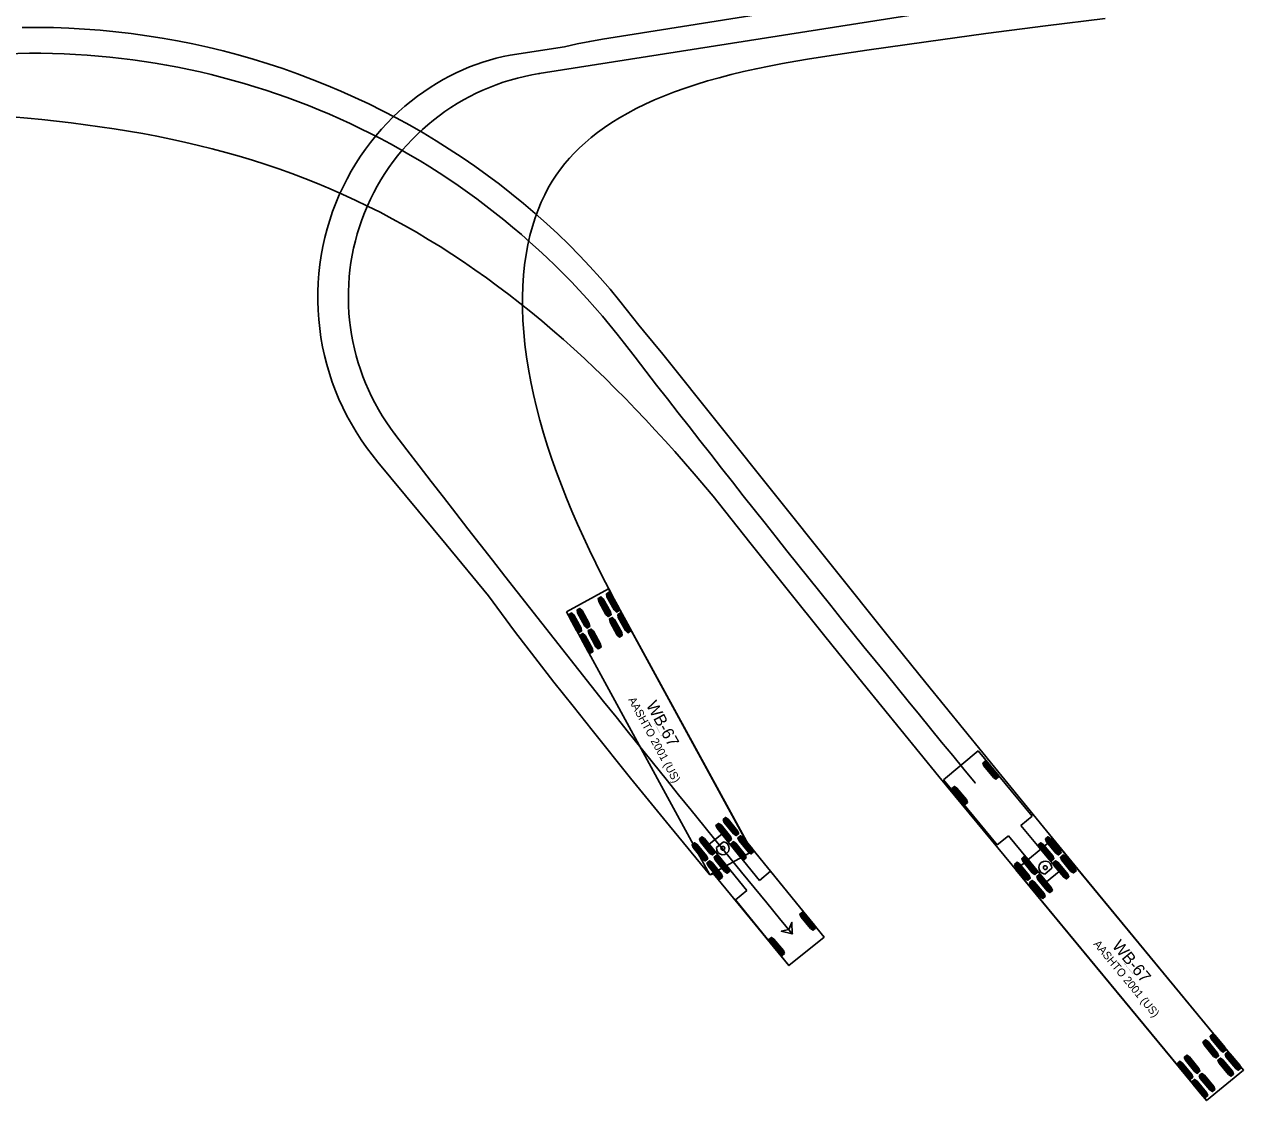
# Model space of a CAD drawing. Extents: x 1639988 to 1641860, y 841974 to 844187.
# Drawn here: x 1640960 to 1641175.9, y 842500.3 to 842690.9 of the extents above; entities that cross this region are included whole.
import ezdxf

# ---------------------------------------------------------------- set-up
doc = ezdxf.new("R2010")
doc.units = 0
doc.layers.add('Scratch_Level_1', color=7, linetype='Continuous')

msp = doc.modelspace()

# ---------------------------------------------------------------- linework, layer by layer
at = {"layer": 'Scratch_Level_1'}
for p, q in [((1641139.5, 842696.08), (1641051.19, 842682.18)), ((1641063.48, 842590.91), (1641056.02, 842586.84)), ((1641088.89, 842544.4), (1641063.48, 842590.91)), ((1641063.47, 842586.06), (1641061.71, 842589.28)), ((1641063.67, 842586.17), (1641061.91, 842589.39)), ((1641063.87, 842586.28), (1641062.11, 842589.5)), ((1641064.92, 842586.85), (1641063.16, 842590.07)), ((1641065.12, 842586.96), (1641063.36, 842590.18)), ((1641065.32, 842587.07), (1641063.56, 842590.29)), ((1641056.02, 842586.84), (1641081.43, 842540.32)), ((1641058.66, 842583.44), (1641056.91, 842586.65)), ((1641059.71, 842584.01), (1641057.95, 842587.23)), ((1641059.91, 842584.12), (1641058.15, 842587.34)), ((1641060.11, 842584.23), (1641058.36, 842587.45)), ((1641067.32, 842583.41), (1641065.56, 842586.63)), ((1641058.26, 842583.22), (1641056.5, 842586.44)), ((1641058.46, 842583.33), (1641056.71, 842586.55)), ((1641065.47, 842582.4), (1641063.71, 842585.62)), ((1641065.67, 842582.51), (1641063.91, 842585.73)), ((1641065.87, 842582.62), (1641064.11, 842585.84)), ((1641066.92, 842583.2), (1641065.16, 842586.41)), ((1641067.12, 842583.3), (1641065.36, 842586.52)), ((1641060.26, 842579.56), (1641058.5, 842582.78)), ((1641060.46, 842579.67), (1641058.7, 842582.89)), ((1641060.66, 842579.78), (1641058.9, 842583)), ((1641061.71, 842580.35), (1641059.95, 842583.57)), ((1641061.91, 842580.46), (1641060.15, 842583.68)), ((1641062.11, 842580.57), (1641060.35, 842583.79)), ((1641128.94, 842562.23), (1641122.77, 842557.14)), ((1641138.49, 842550.67), (1641128.94, 842562.23)), ((1641129.79, 842560.13), (1641132.12, 842557.3)), ((1641129.96, 842560.27), (1641132.3, 842557.45)), ((1641130.14, 842560.42), (1641132.47, 842557.59)), ((1641122.77, 842557.14), (1641132.32, 842545.58)), ((1641122.77, 842557.14), (1641122.77, 842557.14)), ((1641124.32, 842555.62), (1641126.66, 842552.79)), ((1641124.5, 842555.76), (1641126.84, 842552.93)), ((1641124.68, 842555.91), (1641127.01, 842553.08)), ((1641086.13, 842547.28), (1641083.82, 842550.12)), ((1641086.31, 842547.42), (1641084, 842550.27)), ((1641086.49, 842547.56), (1641084.18, 842550.41)), ((1641136.51, 842549.04), (1641138.49, 842550.67)), ((1641084.85, 842546.23), (1641082.54, 842549.08)), ((1641085.03, 842546.38), (1641082.72, 842549.22)), ((1641085.21, 842546.52), (1641082.9, 842549.37)), ((1641143.25, 842540.88), (1641136.51, 842549.04)), ((1641080.64, 842542.81), (1641078.32, 842545.65)), ((1641080.81, 842542.95), (1641078.5, 842545.8)), ((1641080.99, 842543.1), (1641078.68, 842545.94)), ((1641081.92, 842543.85), (1641079.6, 842546.69)), ((1641082.09, 842543.99), (1641079.78, 842546.84)), ((1641082.27, 842544.14), (1641079.96, 842546.98)), ((1641083.52, 842547.51), (1641081.29, 842545.71)), ((1641081.29, 842545.71), (1641087.97, 842537.49)), ((1641083.84, 842546.13), (1641082.58, 842545.11)), ((1641090.19, 842539.3), (1641083.52, 842547.51)), ((1641087.48, 842543), (1641085.17, 842545.85)), ((1641087.66, 842543.15), (1641085.35, 842545.99)), ((1641087.84, 842543.29), (1641085.52, 842546.14)), ((1641088.76, 842544.04), (1641086.45, 842546.89)), ((1641088.94, 842544.19), (1641086.63, 842547.03)), ((1641089.12, 842544.33), (1641086.8, 842547.18)), ((1641132.32, 842545.58), (1641134.3, 842547.21)), ((1641134.3, 842547.21), (1641141.04, 842539.05)), ((1641142.18, 842546.59), (1641135.63, 842541.18)), ((1641139.6, 842545.65), (1641141.94, 842542.82)), ((1641139.78, 842545.79), (1641142.12, 842542.97)), ((1641139.96, 842545.94), (1641142.29, 842543.11)), ((1641140.88, 842546.7), (1641143.21, 842543.87)), ((1641141.05, 842546.84), (1641143.39, 842544.02)), ((1641141.23, 842546.99), (1641143.56, 842544.16)), ((1641175.93, 842505.72), (1641142.18, 842546.59)), ((1641081.43, 842540.32), (1641088.89, 842544.4)), ((1641084.54, 842540.62), (1641082.23, 842543.46)), ((1641084.72, 842540.76), (1641082.41, 842543.61)), ((1641084.9, 842540.9), (1641082.59, 842543.75)), ((1641088.89, 842544.4), (1641088.89, 842544.4)), ((1641136.86, 842543.38), (1641139.2, 842540.56)), ((1641137.04, 842543.53), (1641139.38, 842540.7)), ((1641143.53, 842543.49), (1641145.86, 842540.66)), ((1641143.71, 842543.63), (1641146.04, 842540.8)), ((1641143.88, 842543.78), (1641146.22, 842540.95)), ((1641083.26, 842539.57), (1641080.95, 842542.42)), ((1641083.44, 842539.72), (1641081.13, 842542.57)), ((1641083.62, 842539.86), (1641081.31, 842542.71)), ((1641135.42, 842542.19), (1641137.75, 842539.36)), ((1641135.59, 842542.33), (1641137.93, 842539.51)), ((1641135.77, 842542.48), (1641138.1, 842539.65)), ((1641136.69, 842543.24), (1641139.02, 842540.41)), ((1641140.71, 842540.43), (1641141.95, 842541.46)), ((1641142.26, 842542.43), (1641144.59, 842539.61)), ((1641142.43, 842542.58), (1641144.77, 842539.75)), ((1641142.61, 842542.73), (1641144.95, 842539.9)), ((1641092.18, 842540.92), (1641090.19, 842539.3)), ((1641101.64, 842529.28), (1641092.18, 842540.92)), ((1641135.63, 842541.18), (1641169.38, 842500.31)), ((1641135.63, 842541.18), (1641135.63, 842541.18)), ((1641138.25, 842539.12), (1641140.58, 842536.29)), ((1641138.42, 842539.27), (1641140.76, 842536.44)), ((1641139.34, 842540.03), (1641141.68, 842537.2)), ((1641139.52, 842540.17), (1641141.85, 842537.34)), ((1641139.69, 842540.32), (1641142.03, 842537.49)), ((1641141.04, 842539.05), (1641143.25, 842540.88)), ((1641087.97, 842537.49), (1641085.98, 842535.87)), ((1641138.07, 842538.97), (1641140.4, 842536.15)), ((1641085.98, 842535.87), (1641095.43, 842524.23)), ((1641099.75, 842530.53), (1641097.42, 842533.36)), ((1641099.93, 842530.68), (1641097.59, 842533.51)), ((1641100.11, 842530.83), (1641097.77, 842533.65)), ((1641094.26, 842526.06), (1641091.93, 842528.89)), ((1641094.44, 842526.21), (1641092.1, 842529.04)), ((1641094.61, 842526.35), (1641092.28, 842529.18)), ((1641095.43, 842524.23), (1641101.64, 842529.28)), ((1641101.64, 842529.28), (1641101.64, 842529.28)), ((1641169.13, 842511.02), (1641171.46, 842508.19)), ((1641170.04, 842511.78), (1641172.38, 842508.95)), ((1641170.22, 842511.92), (1641172.56, 842509.09)), ((1641170.4, 842512.07), (1641172.73, 842509.24)), ((1641168.77, 842510.72), (1641171.11, 842507.9)), ((1641168.95, 842510.87), (1641171.28, 842508.04)), ((1641173.05, 842508.85), (1641175.39, 842506.03)), ((1641164.2, 842506.95), (1641166.53, 842504.12)), ((1641164.37, 842507.09), (1641166.71, 842504.27)), ((1641164.55, 842507.24), (1641166.89, 842504.41)), ((1641165.47, 842508), (1641167.8, 842505.17)), ((1641165.65, 842508.14), (1641167.98, 842505.32)), ((1641165.82, 842508.29), (1641168.16, 842505.46)), ((1641171.43, 842507.51), (1641173.76, 842504.69)), ((1641171.6, 842507.66), (1641173.94, 842504.83)), ((1641171.78, 842507.8), (1641174.11, 842504.98)), ((1641172.7, 842508.56), (1641175.03, 842505.74)), ((1641172.87, 842508.71), (1641175.21, 842505.88)), ((1641168.12, 842504.78), (1641170.46, 842501.96)), ((1641168.3, 842504.93), (1641170.63, 842502.1)), ((1641168.48, 842505.08), (1641170.81, 842502.25)), ((1641169.38, 842500.31), (1641175.93, 842505.72)), ((1641166.85, 842503.73), (1641169.19, 842500.91)), ((1641167.03, 842503.88), (1641169.36, 842501.05)), ((1641167.2, 842504.03), (1641169.54, 842501.2))]:
    msp.add_line(p, q, dxfattribs=at)
for points in [[(1641151.4, 842691.94), (1641140.84, 842690.63), (1641130.29, 842689.25), (1641119.74, 842687.81), (1641109.22, 842686.33), (1641104.09, 842685.57), (1641099.09, 842684.78), (1641096.65, 842684.37), (1641094.26, 842683.94), (1641091.91, 842683.49), (1641089.62, 842683.02), (1641087.38, 842682.52), (1641085.19, 842682), (1641083.07, 842681.45), (1641081, 842680.87), (1641079, 842680.26), (1641077.06, 842679.62), (1641075.19, 842678.95), (1641073.38, 842678.25), (1641071.65, 842677.52), (1641069.98, 842676.76), (1641068.39, 842675.98), (1641066.87, 842675.17), (1641065.43, 842674.34), (1641064.06, 842673.49), (1641062.76, 842672.62), (1641061.54, 842671.74), (1641060.4, 842670.84), (1641059.32, 842669.93), (1641058.33, 842669.02), (1641057.41, 842668.11), (1641056.55, 842667.19), (1641055.73, 842666.24), (1641054.95, 842665.24), (1641054.21, 842664.2), (1641053.5, 842663.1), (1641052.82, 842661.95), (1641052.18, 842660.73), (1641051.57, 842659.43), (1641051, 842658.07), (1641050.48, 842656.63), (1641050, 842655.12), (1641049.57, 842653.53), (1641049.2, 842651.87), (1641048.88, 842650.14), (1641048.62, 842648.34), (1641048.43, 842646.48), (1641048.3, 842644.56), (1641048.24, 842642.58), (1641048.24, 842640.55), (1641048.32, 842638.48), (1641048.46, 842636.37), (1641048.67, 842634.22), (1641048.96, 842632.03), (1641049.3, 842629.83), (1641049.72, 842627.59), (1641050.19, 842625.34), (1641050.73, 842623.08), (1641051.33, 842620.8), (1641051.98, 842618.51), (1641052.7, 842616.21), (1641053.46, 842613.91), (1641054.27, 842611.6), (1641055.14, 842609.29), (1641056.05, 842606.99), (1641057, 842604.68), (1641057.99, 842602.38), (1641059.03, 842600.08), (1641060.1, 842597.78), (1641061.21, 842595.49), (1641062.35, 842593.21), (1641063.52, 842590.93), (1641064.73, 842588.65), (1641087.87, 842546.25), (1641088.05, 842545.99), (1641101.64, 842529.28), (1641095.43, 842524.23), (1641088.6, 842532.5), (1641082.06, 842540.48), (1641081.43, 842540.32), (1641074.29, 842548.99), (1641067.4, 842557.42), (1641060.57, 842565.89), (1641057.19, 842570.14), (1641053.82, 842574.4), (1641050.44, 842578.75), (1641046.86, 842583.43), (1641042.2, 842589.68), (1641034.74, 842598.79), (1641022.66, 842613.35), (1641021.62, 842614.65), (1641020.62, 842615.98), (1641019.67, 842617.33), (1641018.78, 842618.72), (1641017.94, 842620.13), (1641017.16, 842621.56), (1641016.43, 842623.03), (1641015.75, 842624.51), (1641015.13, 842626.02), (1641014.56, 842627.55), (1641014.05, 842629.09), (1641013.59, 842630.65), (1641013.19, 842632.23), (1641012.85, 842633.82), (1641012.56, 842635.42), (1641012.34, 842637.03), (1641012.17, 842638.65), (1641012.06, 842640.27), (1641012, 842641.89), (1641012.01, 842643.51), (1641012.07, 842645.14), (1641012.19, 842646.75), (1641012.37, 842648.36), (1641012.61, 842649.96), (1641012.9, 842651.55), (1641013.25, 842653.13), (1641013.66, 842654.68), (1641014.12, 842656.22), (1641014.63, 842657.74), (1641015.19, 842659.23), (1641015.81, 842660.69), (1641016.47, 842662.12), (1641017.18, 842663.53), (1641017.93, 842664.9), (1641018.73, 842666.23), (1641019.56, 842667.53), (1641020.44, 842668.78), (1641021.35, 842670), (1641022.29, 842671.18), (1641023.27, 842672.31), (1641024.27, 842673.4), (1641025.3, 842674.44), (1641026.35, 842675.44), (1641027.43, 842676.39), (1641028.52, 842677.29), (1641029.63, 842678.15), (1641030.76, 842678.96), (1641031.89, 842679.73), (1641033.03, 842680.45), (1641034.19, 842681.12), (1641035.35, 842681.74), (1641036.51, 842682.32), (1641037.68, 842682.86), (1641038.85, 842683.35), (1641040.02, 842683.8), (1641041.2, 842684.2), (1641042.4, 842684.57), (1641043.61, 842684.9), (1641044.84, 842685.18), (1641046.08, 842685.42), (1641055.69, 842686.94), (1641057.92, 842687.42), (1641060.16, 842687.86), (1641062.4, 842688.26), (1641066.92, 842689), (1641105.61, 842695.11)], [(1640959.66, 842690.34), (1640962.42, 842690.36), (1640965.18, 842690.31), (1640967.94, 842690.22), (1640970.7, 842690.06), (1640973.46, 842689.86), (1640976.22, 842689.59), (1640978.97, 842689.27), (1640981.7, 842688.89), (1640984.43, 842688.46), (1640987.15, 842687.98), (1640989.86, 842687.43), (1640992.56, 842686.84), (1640995.25, 842686.19), (1640997.92, 842685.48), (1641000.58, 842684.72), (1641003.22, 842683.91), (1641005.83, 842683.05), (1641008.43, 842682.13), (1641011, 842681.16), (1641013.55, 842680.15), (1641016.07, 842679.08), (1641018.57, 842677.97), (1641021.03, 842676.81), (1641023.48, 842675.59), (1641025.9, 842674.33), (1641028.29, 842673.02), (1641030.65, 842671.67), (1641032.99, 842670.27), (1641035.29, 842668.82), (1641037.56, 842667.32), (1641039.8, 842665.78), (1641042.01, 842664.2), (1641044.18, 842662.57), (1641046.32, 842660.9), (1641048.42, 842659.19), (1641050.48, 842657.43), (1641052.51, 842655.63), (1641054.49, 842653.79), (1641056.43, 842651.91), (1641058.34, 842649.99), (1641060.19, 842648.03), (1641062.01, 842646.02), (1641063.77, 842643.98), (1641065.49, 842641.9), (1641068.83, 842637.65), (1641069.66, 842636.6), (1641071.38, 842634.55), (1641073.07, 842632.48), (1641112.99, 842582.57), (1641119.67, 842574.29), (1641126.37, 842566.02), (1641133.1, 842557.76), (1641146.59, 842541.29), (1641160.14, 842524.85), (1641175.93, 842505.72), (1641169.38, 842500.31), (1641169.28, 842500.43), (1641169.28, 842500.43)], [(1641169.28, 842500.43), (1641128.76, 842549.5), (1641121.99, 842557.73), (1641115.23, 842565.98), (1641108.5, 842574.26), (1641101.79, 842582.55), (1641095.12, 842590.86), (1641088.52, 842599.14), (1641082, 842607.37), (1641078.63, 842611.33), (1641075.21, 842615.23), (1641073.49, 842617.15), (1641071.75, 842619.05), (1641070, 842620.93), (1641068.24, 842622.78), (1641066.46, 842624.62), (1641064.67, 842626.43), (1641062.87, 842628.22), (1641061.04, 842629.98), (1641059.21, 842631.71), (1641057.35, 842633.42), (1641055.48, 842635.1), (1641053.58, 842636.75), (1641051.68, 842638.37), (1641049.75, 842639.96), (1641047.8, 842641.52), (1641045.84, 842643.05), (1641043.85, 842644.55), (1641041.85, 842646.01), (1641039.83, 842647.44), (1641037.79, 842648.84), (1641035.74, 842650.2), (1641033.66, 842651.53), (1641031.57, 842652.82), (1641029.46, 842654.07), (1641027.33, 842655.29), (1641025.18, 842656.47), (1641023.02, 842657.61), (1641020.83, 842658.71), (1641018.64, 842659.77), (1641016.43, 842660.79), (1641014.2, 842661.78), (1641011.96, 842662.72), (1641009.7, 842663.62), (1641007.42, 842664.48), (1641005.12, 842665.31), (1641002.79, 842666.09), (1641000.45, 842666.84), (1640998.08, 842667.55), (1640995.7, 842668.22), (1640993.29, 842668.86), (1640990.87, 842669.46), (1640988.42, 842670.03), (1640985.96, 842670.57), (1640983.49, 842671.07), (1640981, 842671.54), (1640978.49, 842671.97), (1640975.97, 842672.38), (1640973.43, 842672.76), (1640970.88, 842673.12), (1640968.31, 842673.44), (1640965.74, 842673.75), (1640963.16, 842674.02), (1640960.57, 842674.28), (1640957.97, 842674.51)], [(1641096.02, 842529.86), (1641095.94, 842531.86), (1641095.38, 842530.63), (1641094.07, 842530.31), (1641096.02, 842529.86)]]:
    msp.add_lwpolyline(points, dxfattribs=at)
for points in [[(1641063.92, 842586.31), (1641063.42, 842586.03), (1641063.02, 842586.4), (1641061.76, 842588.72), (1641061.66, 842589.25), (1641062.16, 842589.53), (1641062.56, 842589.16), (1641063.83, 842586.84)], [(1641065.37, 842587.1), (1641064.87, 842586.82), (1641064.47, 842587.19), (1641063.21, 842589.51), (1641063.11, 842590.04), (1641063.61, 842590.32), (1641064.01, 842589.95), (1641065.28, 842587.63)], [(1641058.71, 842583.46), (1641058.21, 842583.19), (1641057.82, 842583.56), (1641056.55, 842585.87), (1641056.46, 842586.41), (1641056.96, 842586.68), (1641057.35, 842586.31), (1641058.62, 842584)], [(1641060.16, 842584.25), (1641059.66, 842583.98), (1641059.26, 842584.35), (1641058, 842586.67), (1641057.9, 842587.2), (1641058.41, 842587.47), (1641058.8, 842587.11), (1641060.07, 842584.79)], [(1641067.37, 842583.44), (1641066.87, 842583.17), (1641066.47, 842583.54), (1641065.2, 842585.85), (1641065.11, 842586.39), (1641065.61, 842586.66), (1641066.01, 842586.29), (1641067.27, 842583.98)], [(1641065.92, 842582.65), (1641065.42, 842582.38), (1641065.02, 842582.74), (1641063.75, 842585.06), (1641063.66, 842585.6), (1641064.16, 842585.87), (1641064.56, 842585.5), (1641065.82, 842583.18)], [(1641060.71, 842579.81), (1641060.21, 842579.53), (1641059.81, 842579.9), (1641058.55, 842582.22), (1641058.45, 842582.75), (1641058.95, 842583.03), (1641059.35, 842582.66), (1641060.62, 842580.34)], [(1641062.16, 842580.6), (1641061.66, 842580.32), (1641061.26, 842580.69), (1641060, 842583.01), (1641059.9, 842583.54), (1641060.4, 842583.82), (1641060.8, 842583.45), (1641062.07, 842581.13)], [(1641129.74, 842560.09), (1641130.18, 842560.45), (1641130.64, 842560.17), (1641132.32, 842558.13), (1641132.52, 842557.63), (1641132.08, 842557.26), (1641131.62, 842557.55), (1641129.94, 842559.58)], [(1641124.28, 842555.58), (1641124.72, 842555.94), (1641125.18, 842555.66), (1641126.86, 842553.62), (1641127.06, 842553.12), (1641126.62, 842552.75), (1641126.16, 842553.04), (1641124.47, 842555.07)], [(1641086.53, 842547.6), (1641086.09, 842547.24), (1641085.63, 842547.53), (1641083.97, 842549.58), (1641083.78, 842550.09), (1641084.22, 842550.45), (1641084.68, 842550.16), (1641086.34, 842548.11)], [(1641085.25, 842546.56), (1641084.81, 842546.2), (1641084.35, 842546.49), (1641082.69, 842548.54), (1641082.5, 842549.04), (1641082.94, 842549.41), (1641083.4, 842549.12), (1641085.06, 842547.07)], [(1641081.04, 842543.13), (1641080.59, 842542.77), (1641080.13, 842543.06), (1641078.47, 842545.11), (1641078.28, 842545.62), (1641078.72, 842545.98), (1641079.18, 842545.69), (1641080.85, 842543.64)], [(1641082.32, 842544.17), (1641081.87, 842543.81), (1641081.41, 842544.1), (1641079.75, 842546.15), (1641079.56, 842546.66), (1641080, 842547.02), (1641080.46, 842546.73), (1641082.13, 842544.68)], [(1641087.88, 842543.33), (1641087.44, 842542.96), (1641086.98, 842543.25), (1641085.31, 842545.3), (1641085.12, 842545.81), (1641085.57, 842546.17), (1641086.03, 842545.88), (1641087.69, 842543.83)], [(1641089.16, 842544.37), (1641088.72, 842544.01), (1641088.26, 842544.3), (1641086.59, 842546.34), (1641086.4, 842546.85), (1641086.85, 842547.21), (1641087.31, 842546.92), (1641088.97, 842544.87)], [(1641139.56, 842545.61), (1641140, 842545.98), (1641140.46, 842545.69), (1641142.14, 842543.65), (1641142.34, 842543.15), (1641141.9, 842542.78), (1641141.44, 842543.07), (1641139.75, 842545.11)], [(1641140.83, 842546.66), (1641141.27, 842547.03), (1641141.73, 842546.74), (1641143.41, 842544.7), (1641143.61, 842544.2), (1641143.17, 842543.83), (1641142.71, 842544.12), (1641141.03, 842546.16)], [(1641084.94, 842540.94), (1641084.5, 842540.58), (1641084.04, 842540.87), (1641082.38, 842542.92), (1641082.19, 842543.43), (1641082.63, 842543.79), (1641083.09, 842543.5), (1641084.75, 842541.45)], [(1641136.64, 842543.2), (1641137.08, 842543.57), (1641137.54, 842543.28), (1641139.23, 842541.24), (1641139.42, 842540.74), (1641138.98, 842540.37), (1641138.52, 842540.66), (1641136.84, 842542.7)], [(1641143.49, 842543.45), (1641143.93, 842543.81), (1641144.39, 842543.53), (1641146.07, 842541.49), (1641146.26, 842540.99), (1641145.82, 842540.62), (1641145.36, 842540.91), (1641143.68, 842542.94)], [(1641083.66, 842539.9), (1641083.22, 842539.54), (1641082.76, 842539.83), (1641081.1, 842541.88), (1641080.91, 842542.38), (1641081.35, 842542.75), (1641081.81, 842542.46), (1641083.47, 842540.41)], [(1641135.37, 842542.15), (1641135.81, 842542.52), (1641136.27, 842542.23), (1641137.95, 842540.19), (1641138.15, 842539.69), (1641137.71, 842539.32), (1641137.25, 842539.61), (1641135.57, 842541.65)], [(1641142.21, 842542.4), (1641142.65, 842542.76), (1641143.11, 842542.48), (1641144.8, 842540.44), (1641144.99, 842539.94), (1641144.55, 842539.57), (1641144.09, 842539.86), (1641142.41, 842541.89)], [(1641138.02, 842538.94), (1641138.47, 842539.3), (1641138.93, 842539.02), (1641140.61, 842536.98), (1641140.8, 842536.48), (1641140.36, 842536.11), (1641139.9, 842536.4), (1641138.22, 842538.43)], [(1641139.3, 842539.99), (1641139.74, 842540.35), (1641140.2, 842540.07), (1641141.88, 842538.03), (1641142.07, 842537.53), (1641141.63, 842537.16), (1641141.17, 842537.45), (1641139.49, 842539.48)], [(1641100.15, 842530.86), (1641099.71, 842530.5), (1641099.25, 842530.78), (1641097.57, 842532.82), (1641097.37, 842533.33), (1641097.82, 842533.69), (1641098.28, 842533.4), (1641099.96, 842531.37)], [(1641096.02, 842529.86), (1641095.94, 842531.86), (1641095.38, 842530.63), (1641094.07, 842530.31)], [(1641094.66, 842526.39), (1641094.22, 842526.03), (1641093.76, 842526.31), (1641092.08, 842528.35), (1641091.88, 842528.85), (1641092.32, 842529.22), (1641092.78, 842528.93), (1641094.46, 842526.9)], [(1641168.73, 842510.69), (1641169.17, 842511.05), (1641169.63, 842510.77), (1641171.31, 842508.73), (1641171.5, 842508.23), (1641171.06, 842507.86), (1641170.6, 842508.15), (1641168.92, 842510.18)], [(1641170, 842511.74), (1641170.44, 842512.1), (1641170.9, 842511.82), (1641172.58, 842509.78), (1641172.78, 842509.28), (1641172.34, 842508.91), (1641171.88, 842509.2), (1641170.19, 842511.23)], [(1641172.65, 842508.53), (1641173.09, 842508.89), (1641173.55, 842508.61), (1641175.24, 842506.57), (1641175.43, 842506.06), (1641174.99, 842505.7), (1641174.53, 842505.99), (1641172.85, 842508.02)], [(1641164.15, 842506.91), (1641164.59, 842507.27), (1641165.05, 842506.99), (1641166.74, 842504.95), (1641166.93, 842504.45), (1641166.49, 842504.08), (1641166.03, 842504.37), (1641164.35, 842506.4)], [(1641165.43, 842507.96), (1641165.87, 842508.33), (1641166.33, 842508.04), (1641168.01, 842506), (1641168.2, 842505.5), (1641167.76, 842505.13), (1641167.3, 842505.42), (1641165.62, 842507.46)], [(1641171.38, 842507.48), (1641171.82, 842507.84), (1641172.28, 842507.55), (1641173.96, 842505.52), (1641174.16, 842505.01), (1641173.72, 842504.65), (1641173.26, 842504.94), (1641171.58, 842506.97)], [(1641168.08, 842504.75), (1641168.52, 842505.11), (1641168.98, 842504.83), (1641170.66, 842502.79), (1641170.85, 842502.29), (1641170.41, 842501.92), (1641169.95, 842502.21), (1641168.27, 842504.24)], [(1641166.81, 842503.7), (1641167.25, 842504.06), (1641167.71, 842503.78), (1641169.39, 842501.74), (1641169.58, 842501.23), (1641169.14, 842500.87), (1641168.68, 842501.16), (1641167, 842503.19)]]:
    msp.add_lwpolyline(points, close=True, dxfattribs=at)
for centre, radius in [((1641051.19, 842682.18), 0.0417), ((1641051.19, 842682.18), 0.0417), ((1641066.29, 842634.4), 0.0417), ((1641066.29, 842634.4), 0.0417), ((1641025.65, 842618.36), 0.0417), ((1641025.65, 842618.36), 0.0417), ((1641128.4, 842556.6), 0.0417), ((1641083.72, 842544.99), 0.34), ((1641140.82, 842541.57), 0.34), ((1641096.02, 842529.86), 0.0417)]:
    msp.add_circle(centre, radius, dxfattribs=at)
for centre, radius, start, end in [((1640961.78, 842553.77), 132, 37.6529, 93.9449), ((1641057.41, 842642.66), 40, 98.9449, 217.4246), ((1643441.46, 844467.03), 3000, 217.65289, 219.55428), ((1643441.46, 844467.03), 3042, 217.4246, 219.55428), ((1641083.72, 842544.99), 1.14, 174.0915, 84.0915), ((1641140.82, 842541.57), 1.14, 354.5543, 264.5543)]:
    msp.add_arc(centre, radius, start, end, dxfattribs=at)

# ---------------------------------------------------------------- texts
for s, height, rotation, p in [('AASHTO 2001 (US)', 1.4167, 298.6408, (1641066.91, 842571.32)), ('WB-67', 2.125, 298.6408, (1641070.06, 842570.36)), ('(c) 2019 Transoft Solutions, Inc. All rights reserved.', 0.085, 298.6408, (1641071.59, 842567.12)), ('AASHTO 2001 (US)', 1.4167, 309.5543, (1641149.26, 842528)), ('WB-67', 2.125, 309.5543, (1641152.53, 842527.65)), ('(c) 2019 Transoft Solutions, Inc. All rights reserved.', 0.085, 309.5543, (1641154.65, 842524.76))]:
    msp.add_text(s, height=height, rotation=rotation, dxfattribs=at).set_placement(p)

doc.saveas('drawing.dxf')
